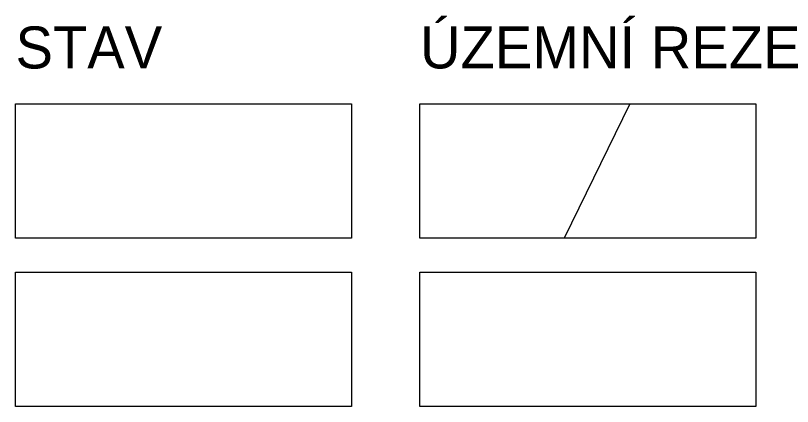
# Model space of a CAD drawing. Extents: x -443494 to -430443, y -1146902 to -1140081.
# Drawn here: x -436264.6 to -436024.1, y -1145334 to -1145212.9 of the extents above; entities that cross this region are included whole.
import ezdxf

# ---------------------------------------------------------------- set-up
doc = ezdxf.new("R2010")
doc.units = 0
doc.layers.add('Vrstva 1', color=7, linetype='Continuous')

msp = doc.modelspace()

# ---------------------------------------------------------------- linework, layer by layer
at = {"layer": 'Vrstva 1'}
msp.add_line((-436074.487, -1145240.299), (-436094.764, -1145281.899), dxfattribs=at)
for points in [[(-436264.621, -1145240.299), (-436160.621, -1145240.299), (-436160.621, -1145281.899), (-436264.621, -1145281.899)], [(-436264.621, -1145240.299), (-436160.621, -1145240.299), (-436160.621, -1145281.899), (-436264.621, -1145281.899)], [(-436264.621, -1145240.299), (-436160.621, -1145240.299), (-436160.621, -1145281.899), (-436264.621, -1145281.899)], [(-436264.621, -1145240.299), (-436160.621, -1145240.299), (-436160.621, -1145281.899), (-436264.621, -1145281.899)], [(-436264.621, -1145240.299), (-436160.621, -1145240.299), (-436160.621, -1145281.899), (-436264.621, -1145281.899)], [(-436264.621, -1145240.299), (-436160.621, -1145240.299), (-436160.621, -1145281.899), (-436264.621, -1145281.899)], [(-436264.621, -1145240.299), (-436160.621, -1145240.299), (-436160.621, -1145281.899), (-436264.621, -1145281.899)], [(-436264.621, -1145240.299), (-436160.621, -1145240.299), (-436160.621, -1145281.899), (-436264.621, -1145281.899)], [(-436264.621, -1145240.299), (-436160.621, -1145240.299), (-436160.621, -1145281.899), (-436264.621, -1145281.899)], [(-436264.621, -1145240.299), (-436160.621, -1145240.299), (-436160.621, -1145281.899), (-436264.621, -1145281.899)], [(-436264.621, -1145240.299), (-436160.621, -1145240.299), (-436160.621, -1145281.899), (-436264.621, -1145281.899)], [(-436264.621, -1145240.299), (-436160.621, -1145240.299), (-436160.621, -1145281.899), (-436264.621, -1145281.899)], [(-436264.621, -1145240.299), (-436160.621, -1145240.299), (-436160.621, -1145281.899), (-436264.621, -1145281.899)], [(-436264.621, -1145240.299), (-436160.621, -1145240.299), (-436160.621, -1145281.899), (-436264.621, -1145281.899)], [(-436264.621, -1145240.299), (-436160.621, -1145240.299), (-436160.621, -1145281.899), (-436264.621, -1145281.899)], [(-436264.621, -1145240.299), (-436160.621, -1145240.299), (-436160.621, -1145281.899), (-436264.621, -1145281.899)], [(-436264.621, -1145240.299), (-436160.621, -1145240.299), (-436160.621, -1145281.899), (-436264.621, -1145281.899)], [(-436264.621, -1145240.299), (-436160.621, -1145240.299), (-436160.621, -1145281.899), (-436264.621, -1145281.899)], [(-436264.621, -1145240.299), (-436160.621, -1145240.299), (-436160.621, -1145281.899), (-436264.621, -1145281.899)], [(-436264.621, -1145240.299), (-436160.621, -1145240.299), (-436160.621, -1145281.899), (-436264.621, -1145281.899)], [(-436264.621, -1145240.299), (-436160.621, -1145240.299), (-436160.621, -1145281.899), (-436264.621, -1145281.899)], [(-436264.621, -1145240.299), (-436160.621, -1145240.299), (-436160.621, -1145281.899), (-436264.621, -1145281.899)], [(-436264.621, -1145240.299), (-436160.621, -1145240.299), (-436160.621, -1145281.899), (-436264.621, -1145281.899)], [(-436264.621, -1145240.299), (-436160.621, -1145240.299), (-436160.621, -1145281.899), (-436264.621, -1145281.899)], [(-436264.621, -1145240.299), (-436160.621, -1145240.299), (-436160.621, -1145281.899), (-436264.621, -1145281.899)], [(-436264.621, -1145240.299), (-436160.621, -1145240.299), (-436160.621, -1145281.899), (-436264.621, -1145281.899)], [(-436264.621, -1145240.299), (-436160.621, -1145240.299), (-436160.621, -1145281.899), (-436264.621, -1145281.899)], [(-436264.621, -1145240.299), (-436160.621, -1145240.299), (-436160.621, -1145281.899), (-436264.621, -1145281.899)], [(-436264.621, -1145240.299), (-436160.621, -1145240.299), (-436160.621, -1145281.899), (-436264.621, -1145281.899)], [(-436264.621, -1145240.299), (-436160.621, -1145240.299), (-436160.621, -1145281.899), (-436264.621, -1145281.899)], [(-436264.621, -1145240.299), (-436160.621, -1145240.299), (-436160.621, -1145281.899), (-436264.621, -1145281.899)], [(-436264.621, -1145240.299), (-436160.621, -1145240.299), (-436160.621, -1145281.899), (-436264.621, -1145281.899)], [(-436139.429, -1145240.299), (-436035.429, -1145240.299), (-436035.429, -1145281.899), (-436139.429, -1145281.899)], [(-436139.429, -1145240.299), (-436035.429, -1145240.299), (-436035.429, -1145281.899), (-436139.429, -1145281.899)], [(-436139.429, -1145240.299), (-436035.429, -1145240.299), (-436035.429, -1145281.899), (-436139.429, -1145281.899)], [(-436139.429, -1145240.299), (-436035.429, -1145240.299), (-436035.429, -1145281.899), (-436139.429, -1145281.899)], [(-436139.429, -1145240.299), (-436035.429, -1145240.299), (-436035.429, -1145281.899), (-436139.429, -1145281.899)], [(-436139.429, -1145240.299), (-436035.429, -1145240.299), (-436035.429, -1145281.899), (-436139.429, -1145281.899)], [(-436139.429, -1145240.299), (-436035.429, -1145240.299), (-436035.429, -1145281.899), (-436139.429, -1145281.899)], [(-436139.429, -1145240.299), (-436035.429, -1145240.299), (-436035.429, -1145281.899), (-436139.429, -1145281.899)], [(-436139.429, -1145240.299), (-436035.429, -1145240.299), (-436035.429, -1145281.899), (-436139.429, -1145281.899)], [(-436139.429, -1145240.299), (-436035.429, -1145240.299), (-436035.429, -1145281.899), (-436139.429, -1145281.899)], [(-436139.429, -1145240.299), (-436035.429, -1145240.299), (-436035.429, -1145281.899), (-436139.429, -1145281.899)], [(-436139.429, -1145240.299), (-436035.429, -1145240.299), (-436035.429, -1145281.899), (-436139.429, -1145281.899)], [(-436139.429, -1145240.299), (-436035.429, -1145240.299), (-436035.429, -1145281.899), (-436139.429, -1145281.899)], [(-436139.429, -1145240.299), (-436035.429, -1145240.299), (-436035.429, -1145281.899), (-436139.429, -1145281.899)], [(-436139.429, -1145240.299), (-436035.429, -1145240.299), (-436035.429, -1145281.899), (-436139.429, -1145281.899)], [(-436139.429, -1145240.299), (-436035.429, -1145240.299), (-436035.429, -1145281.899), (-436139.429, -1145281.899)], [(-436139.429, -1145240.299), (-436035.429, -1145240.299), (-436035.429, -1145281.899), (-436139.429, -1145281.899)], [(-436139.429, -1145240.299), (-436035.429, -1145240.299), (-436035.429, -1145281.899), (-436139.429, -1145281.899)], [(-436139.429, -1145240.299), (-436035.429, -1145240.299), (-436035.429, -1145281.899), (-436139.429, -1145281.899)], [(-436139.429, -1145240.299), (-436035.429, -1145240.299), (-436035.429, -1145281.899), (-436139.429, -1145281.899)], [(-436139.429, -1145240.299), (-436035.429, -1145240.299), (-436035.429, -1145281.899), (-436139.429, -1145281.899)], [(-436139.429, -1145240.299), (-436035.429, -1145240.299), (-436035.429, -1145281.899), (-436139.429, -1145281.899)], [(-436139.429, -1145240.299), (-436035.429, -1145240.299), (-436035.429, -1145281.899), (-436139.429, -1145281.899)], [(-436139.429, -1145240.299), (-436035.429, -1145240.299), (-436035.429, -1145281.899), (-436139.429, -1145281.899)], [(-436139.429, -1145240.299), (-436035.429, -1145240.299), (-436035.429, -1145281.899), (-436139.429, -1145281.899)], [(-436139.429, -1145240.299), (-436035.429, -1145240.299), (-436035.429, -1145281.899), (-436139.429, -1145281.899)], [(-436139.429, -1145240.299), (-436035.429, -1145240.299), (-436035.429, -1145281.899), (-436139.429, -1145281.899)], [(-436139.429, -1145240.299), (-436035.429, -1145240.299), (-436035.429, -1145281.899), (-436139.429, -1145281.899)], [(-436139.429, -1145240.299), (-436035.429, -1145240.299), (-436035.429, -1145281.899), (-436139.429, -1145281.899)], [(-436139.429, -1145240.299), (-436035.429, -1145240.299), (-436035.429, -1145281.899), (-436139.429, -1145281.899)], [(-436139.429, -1145240.299), (-436035.429, -1145240.299), (-436035.429, -1145281.899), (-436139.429, -1145281.899)], [(-436139.429, -1145240.299), (-436035.429, -1145240.299), (-436035.429, -1145281.899), (-436139.429, -1145281.899)], [(-436139.429, -1145240.299), (-436035.429, -1145240.299), (-436035.429, -1145281.899), (-436139.429, -1145281.899)], [(-436139.429, -1145240.299), (-436035.429, -1145240.299), (-436035.429, -1145281.899), (-436139.429, -1145281.899)], [(-436139.429, -1145240.299), (-436035.429, -1145240.299), (-436035.429, -1145281.899), (-436139.429, -1145281.899)], [(-436139.429, -1145240.299), (-436035.429, -1145240.299), (-436035.429, -1145281.899), (-436139.429, -1145281.899)], [(-436139.429, -1145240.299), (-436035.429, -1145240.299), (-436035.429, -1145281.899), (-436139.429, -1145281.899)], [(-436139.429, -1145240.299), (-436035.429, -1145240.299), (-436035.429, -1145281.899), (-436139.429, -1145281.899)], [(-436139.429, -1145240.299), (-436035.429, -1145240.299), (-436035.429, -1145281.899), (-436139.429, -1145281.899)], [(-436139.429, -1145240.299), (-436035.429, -1145240.299), (-436035.429, -1145281.899), (-436139.429, -1145281.899)], [(-436139.429, -1145240.299), (-436035.429, -1145240.299), (-436035.429, -1145281.899), (-436139.429, -1145281.899)], [(-436139.429, -1145240.299), (-436035.429, -1145240.299), (-436035.429, -1145281.899), (-436139.429, -1145281.899)], [(-436139.429, -1145240.299), (-436035.429, -1145240.299), (-436035.429, -1145281.899), (-436139.429, -1145281.899)], [(-436139.429, -1145240.299), (-436035.429, -1145240.299), (-436035.429, -1145281.899), (-436139.429, -1145281.899)], [(-436139.429, -1145240.299), (-436035.429, -1145240.299), (-436035.429, -1145281.899), (-436139.429, -1145281.899)], [(-436139.429, -1145240.299), (-436035.429, -1145240.299), (-436035.429, -1145281.899), (-436139.429, -1145281.899)], [(-436139.429, -1145240.299), (-436035.429, -1145240.299), (-436035.429, -1145281.899), (-436139.429, -1145281.899)], [(-436139.429, -1145240.299), (-436035.429, -1145240.299), (-436035.429, -1145281.899), (-436139.429, -1145281.899)], [(-436139.429, -1145240.299), (-436035.429, -1145240.299), (-436035.429, -1145281.899), (-436139.429, -1145281.899)], [(-436139.429, -1145240.299), (-436035.429, -1145240.299), (-436035.429, -1145281.899), (-436139.429, -1145281.899)], [(-436139.429, -1145240.299), (-436035.429, -1145240.299), (-436035.429, -1145281.899), (-436139.429, -1145281.899)], [(-436139.429, -1145240.299), (-436035.429, -1145240.299), (-436035.429, -1145281.899), (-436139.429, -1145281.899)], [(-436139.429, -1145240.299), (-436035.429, -1145240.299), (-436035.429, -1145281.899), (-436139.429, -1145281.899)], [(-436139.429, -1145240.299), (-436035.429, -1145240.299), (-436035.429, -1145281.899), (-436139.429, -1145281.899)], [(-436139.429, -1145240.299), (-436035.429, -1145240.299), (-436035.429, -1145281.899), (-436139.429, -1145281.899)], [(-436139.429, -1145240.299), (-436035.429, -1145240.299), (-436035.429, -1145281.899), (-436139.429, -1145281.899)], [(-436139.429, -1145240.299), (-436035.429, -1145240.299), (-436035.429, -1145281.899), (-436139.429, -1145281.899)], [(-436139.429, -1145240.299), (-436035.429, -1145240.299), (-436035.429, -1145281.899), (-436139.429, -1145281.899)], [(-436139.429, -1145240.299), (-436035.429, -1145240.299), (-436035.429, -1145281.899), (-436139.429, -1145281.899)], [(-436139.429, -1145240.299), (-436035.429, -1145240.299), (-436035.429, -1145281.899), (-436139.429, -1145281.899)], [(-436139.429, -1145240.299), (-436035.429, -1145240.299), (-436035.429, -1145281.899), (-436139.429, -1145281.899)], [(-436139.429, -1145240.299), (-436035.429, -1145240.299), (-436035.429, -1145281.899), (-436139.429, -1145281.899)], [(-436139.429, -1145240.299), (-436035.429, -1145240.299), (-436035.429, -1145281.899), (-436139.429, -1145281.899)], [(-436139.429, -1145240.299), (-436035.429, -1145240.299), (-436035.429, -1145281.899), (-436139.429, -1145281.899)], [(-436139.429, -1145240.299), (-436035.429, -1145240.299), (-436035.429, -1145281.899), (-436139.429, -1145281.899)], [(-436139.429, -1145240.299), (-436035.429, -1145240.299), (-436035.429, -1145281.899), (-436139.429, -1145281.899)], [(-436139.429, -1145240.299), (-436035.429, -1145240.299), (-436035.429, -1145281.899), (-436139.429, -1145281.899)], [(-436139.429, -1145240.299), (-436035.429, -1145240.299), (-436035.429, -1145281.899), (-436139.429, -1145281.899)], [(-436264.621, -1145292.388), (-436160.621, -1145292.388), (-436160.621, -1145333.988), (-436264.621, -1145333.988)], [(-436264.621, -1145292.388), (-436160.621, -1145292.388), (-436160.621, -1145333.988), (-436264.621, -1145333.988)], [(-436264.621, -1145292.388), (-436160.621, -1145292.388), (-436160.621, -1145333.988), (-436264.621, -1145333.988)], [(-436264.621, -1145292.388), (-436160.621, -1145292.388), (-436160.621, -1145333.988), (-436264.621, -1145333.988)], [(-436264.621, -1145292.388), (-436160.621, -1145292.388), (-436160.621, -1145333.988), (-436264.621, -1145333.988)], [(-436264.621, -1145292.388), (-436160.621, -1145292.388), (-436160.621, -1145333.988), (-436264.621, -1145333.988)], [(-436264.621, -1145292.388), (-436160.621, -1145292.388), (-436160.621, -1145333.988), (-436264.621, -1145333.988)], [(-436264.621, -1145292.388), (-436160.621, -1145292.388), (-436160.621, -1145333.988), (-436264.621, -1145333.988)], [(-436264.621, -1145292.388), (-436160.621, -1145292.388), (-436160.621, -1145333.988), (-436264.621, -1145333.988)], [(-436264.621, -1145292.388), (-436160.621, -1145292.388), (-436160.621, -1145333.988), (-436264.621, -1145333.988)], [(-436264.621, -1145292.388), (-436160.621, -1145292.388), (-436160.621, -1145333.988), (-436264.621, -1145333.988)], [(-436264.621, -1145292.388), (-436160.621, -1145292.388), (-436160.621, -1145333.988), (-436264.621, -1145333.988)], [(-436264.621, -1145292.388), (-436160.621, -1145292.388), (-436160.621, -1145333.988), (-436264.621, -1145333.988)], [(-436264.621, -1145292.388), (-436160.621, -1145292.388), (-436160.621, -1145333.988), (-436264.621, -1145333.988)], [(-436264.621, -1145292.388), (-436160.621, -1145292.388), (-436160.621, -1145333.988), (-436264.621, -1145333.988)], [(-436264.621, -1145292.388), (-436160.621, -1145292.388), (-436160.621, -1145333.988), (-436264.621, -1145333.988)], [(-436264.621, -1145292.388), (-436160.621, -1145292.388), (-436160.621, -1145333.988), (-436264.621, -1145333.988)], [(-436264.621, -1145292.388), (-436160.621, -1145292.388), (-436160.621, -1145333.988), (-436264.621, -1145333.988)], [(-436264.621, -1145292.388), (-436160.621, -1145292.388), (-436160.621, -1145333.988), (-436264.621, -1145333.988)], [(-436264.621, -1145292.388), (-436160.621, -1145292.388), (-436160.621, -1145333.988), (-436264.621, -1145333.988)], [(-436264.621, -1145292.388), (-436160.621, -1145292.388), (-436160.621, -1145333.988), (-436264.621, -1145333.988)], [(-436264.621, -1145292.388), (-436160.621, -1145292.388), (-436160.621, -1145333.988), (-436264.621, -1145333.988)], [(-436264.621, -1145292.388), (-436160.621, -1145292.388), (-436160.621, -1145333.988), (-436264.621, -1145333.988)], [(-436264.621, -1145292.388), (-436160.621, -1145292.388), (-436160.621, -1145333.988), (-436264.621, -1145333.988)], [(-436264.621, -1145292.388), (-436160.621, -1145292.388), (-436160.621, -1145333.988), (-436264.621, -1145333.988)], [(-436264.621, -1145292.388), (-436160.621, -1145292.388), (-436160.621, -1145333.988), (-436264.621, -1145333.988)], [(-436264.621, -1145292.388), (-436160.621, -1145292.388), (-436160.621, -1145333.988), (-436264.621, -1145333.988)], [(-436264.621, -1145292.388), (-436160.621, -1145292.388), (-436160.621, -1145333.988), (-436264.621, -1145333.988)], [(-436264.621, -1145292.388), (-436160.621, -1145292.388), (-436160.621, -1145333.988), (-436264.621, -1145333.988)], [(-436264.621, -1145292.388), (-436160.621, -1145292.388), (-436160.621, -1145333.988), (-436264.621, -1145333.988)], [(-436264.621, -1145292.388), (-436160.621, -1145292.388), (-436160.621, -1145333.988), (-436264.621, -1145333.988)], [(-436264.621, -1145292.388), (-436160.621, -1145292.388), (-436160.621, -1145333.988), (-436264.621, -1145333.988)], [(-436139.429, -1145292.388), (-436035.429, -1145292.388), (-436035.429, -1145333.988), (-436139.429, -1145333.988)], [(-436139.429, -1145292.388), (-436035.429, -1145292.388), (-436035.429, -1145333.988), (-436139.429, -1145333.988)], [(-436139.429, -1145292.388), (-436035.429, -1145292.388), (-436035.429, -1145333.988), (-436139.429, -1145333.988)], [(-436139.429, -1145292.388), (-436035.429, -1145292.388), (-436035.429, -1145333.988), (-436139.429, -1145333.988)], [(-436139.429, -1145292.388), (-436035.429, -1145292.388), (-436035.429, -1145333.988), (-436139.429, -1145333.988)], [(-436139.429, -1145292.388), (-436035.429, -1145292.388), (-436035.429, -1145333.988), (-436139.429, -1145333.988)], [(-436139.429, -1145292.388), (-436035.429, -1145292.388), (-436035.429, -1145333.988), (-436139.429, -1145333.988)], [(-436139.429, -1145292.388), (-436035.429, -1145292.388), (-436035.429, -1145333.988), (-436139.429, -1145333.988)], [(-436139.429, -1145292.388), (-436035.429, -1145292.388), (-436035.429, -1145333.988), (-436139.429, -1145333.988)], [(-436139.429, -1145292.388), (-436035.429, -1145292.388), (-436035.429, -1145333.988), (-436139.429, -1145333.988)], [(-436139.429, -1145292.388), (-436035.429, -1145292.388), (-436035.429, -1145333.988), (-436139.429, -1145333.988)], [(-436139.429, -1145292.388), (-436035.429, -1145292.388), (-436035.429, -1145333.988), (-436139.429, -1145333.988)], [(-436139.429, -1145292.388), (-436035.429, -1145292.388), (-436035.429, -1145333.988), (-436139.429, -1145333.988)], [(-436139.429, -1145292.388), (-436035.429, -1145292.388), (-436035.429, -1145333.988), (-436139.429, -1145333.988)], [(-436139.429, -1145292.388), (-436035.429, -1145292.388), (-436035.429, -1145333.988), (-436139.429, -1145333.988)], [(-436139.429, -1145292.388), (-436035.429, -1145292.388), (-436035.429, -1145333.988), (-436139.429, -1145333.988)], [(-436139.429, -1145292.388), (-436035.429, -1145292.388), (-436035.429, -1145333.988), (-436139.429, -1145333.988)], [(-436139.429, -1145292.388), (-436035.429, -1145292.388), (-436035.429, -1145333.988), (-436139.429, -1145333.988)], [(-436139.429, -1145292.388), (-436035.429, -1145292.388), (-436035.429, -1145333.988), (-436139.429, -1145333.988)], [(-436139.429, -1145292.388), (-436035.429, -1145292.388), (-436035.429, -1145333.988), (-436139.429, -1145333.988)], [(-436139.429, -1145292.388), (-436035.429, -1145292.388), (-436035.429, -1145333.988), (-436139.429, -1145333.988)], [(-436139.429, -1145292.388), (-436035.429, -1145292.388), (-436035.429, -1145333.988), (-436139.429, -1145333.988)], [(-436139.429, -1145292.388), (-436035.429, -1145292.388), (-436035.429, -1145333.988), (-436139.429, -1145333.988)], [(-436139.429, -1145292.388), (-436035.429, -1145292.388), (-436035.429, -1145333.988), (-436139.429, -1145333.988)], [(-436139.429, -1145292.388), (-436035.429, -1145292.388), (-436035.429, -1145333.988), (-436139.429, -1145333.988)], [(-436139.429, -1145292.388), (-436035.429, -1145292.388), (-436035.429, -1145333.988), (-436139.429, -1145333.988)], [(-436139.429, -1145292.388), (-436035.429, -1145292.388), (-436035.429, -1145333.988), (-436139.429, -1145333.988)], [(-436139.429, -1145292.388), (-436035.429, -1145292.388), (-436035.429, -1145333.988), (-436139.429, -1145333.988)], [(-436139.429, -1145292.388), (-436035.429, -1145292.388), (-436035.429, -1145333.988), (-436139.429, -1145333.988)], [(-436139.429, -1145292.388), (-436035.429, -1145292.388), (-436035.429, -1145333.988), (-436139.429, -1145333.988)], [(-436139.429, -1145292.388), (-436035.429, -1145292.388), (-436035.429, -1145333.988), (-436139.429, -1145333.988)], [(-436139.429, -1145292.388), (-436035.429, -1145292.388), (-436035.429, -1145333.988), (-436139.429, -1145333.988)]]:
    msp.add_lwpolyline(points, close=True, dxfattribs=at)

# ---------------------------------------------------------------- texts
for s, p in [('ÚZEMNÍ REZERVA', (-436139.429, -1145229.287)), ('STAV', (-436264.621, -1145229.287)), ('STAV', (-436264.621, -1145229.287)), ('STAV', (-436264.621, -1145229.287)), ('STAV', (-436264.621, -1145229.287)), ('STAV', (-436264.621, -1145229.287)), ('STAV', (-436264.621, -1145229.287)), ('STAV', (-436264.621, -1145229.287)), ('STAV', (-436264.621, -1145229.287)), ('STAV', (-436264.621, -1145229.287)), ('STAV', (-436264.621, -1145229.287)), ('STAV', (-436264.621, -1145229.287)), ('STAV', (-436264.621, -1145229.287)), ('STAV', (-436264.621, -1145229.287)), ('STAV', (-436264.621, -1145229.287)), ('STAV', (-436264.621, -1145229.287)), ('STAV', (-436264.621, -1145229.287)), ('STAV', (-436264.621, -1145229.287)), ('STAV', (-436264.621, -1145229.287)), ('STAV', (-436264.621, -1145229.287)), ('STAV', (-436264.621, -1145229.287)), ('STAV', (-436264.621, -1145229.287)), ('STAV', (-436264.621, -1145229.287)), ('STAV', (-436264.621, -1145229.287)), ('STAV', (-436264.621, -1145229.287)), ('STAV', (-436264.621, -1145229.287)), ('STAV', (-436264.621, -1145229.287)), ('STAV', (-436264.621, -1145229.287)), ('STAV', (-436264.621, -1145229.287)), ('STAV', (-436264.621, -1145229.287)), ('STAV', (-436264.621, -1145229.287)), ('STAV', (-436264.621, -1145229.287)), ('STAV', (-436264.621, -1145229.287))]:
    msp.add_text(s, height=12.9974, dxfattribs=at).set_placement(p)

doc.saveas('drawing.dxf')
